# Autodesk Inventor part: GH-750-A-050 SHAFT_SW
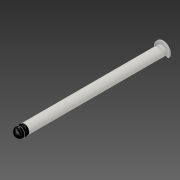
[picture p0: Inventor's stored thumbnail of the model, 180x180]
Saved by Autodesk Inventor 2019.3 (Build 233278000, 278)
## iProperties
Created: 2018-11
Part Number: GH-750-A-050 SHAFT_SW
Material: Generic
Document SubType Name: Modeling
Designer: Justin
Density: 1 g/cm^3
Appearance: Default
Author: Justin
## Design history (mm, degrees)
node "Assembly1" dims "d0" = 10
body "Solid1"
node "Part1:1" dims "d0" = 10
node "Part2:1" dims "d0" = 10
body "Solid2"
node "Part3:1" dims "d0" = 10
body "Solid3"
